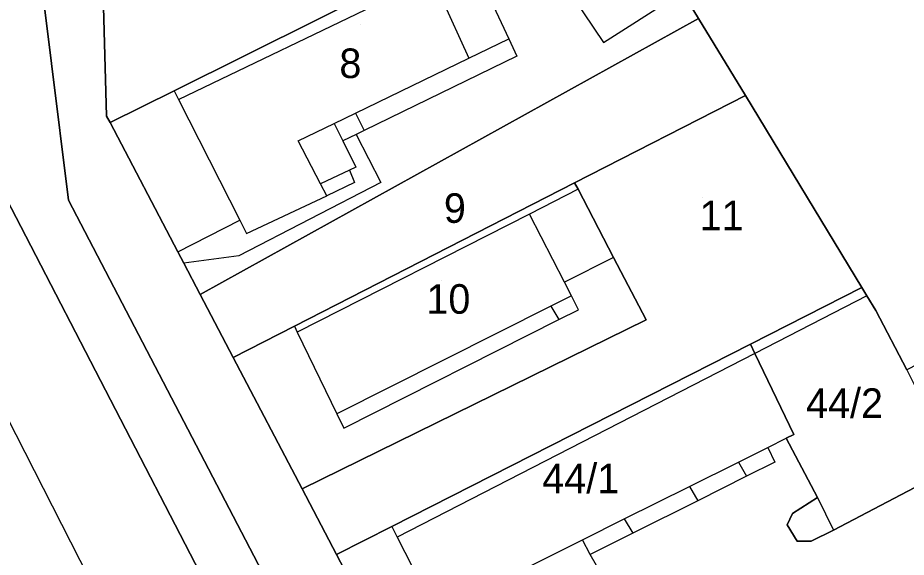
# Model space of a CAD drawing. Extents: x -263943 to -261149, y -1236934 to -1230686.
# Drawn here: x -262965.3 to -262905.2, y -1235602.8 to -1235566.2 of the extents above; entities that cross this region are included whole.
import ezdxf

# ---------------------------------------------------------------- set-up
doc = ezdxf.new("R2010")
doc.units = 0
for name, color, linetype in [('body_kn', 7, 'Continuous'), ('kladpar_druhypozemkov', 7, 'Continuous'), ('kladpar_hranice', 7, 'Continuous'), ('kladpar_parcelnecisla', 7, 'Continuous'), ('kladpar_plochy', 7, 'Continuous'), ('zappar_hrandruhpozemk', 7, 'Continuous'), ('zuob_linie', 7, 'Continuous'), ('zuob_plochy', 7, 'Continuous')]:
    doc.layers.add(name, color=color, linetype=linetype)

msp = doc.modelspace()

# ---------------------------------------------------------------- linework, layer by layer
at = {"layer": 'body_kn'}
for p, q in [((-262919.25, -1235566.29), (-262919.25, -1235566.29)), ((-262932.1, -1235567.68), (-262932.1, -1235567.68)), ((-262925.69, -1235567.93), (-262925.69, -1235567.93)), ((-262931.55, -1235568.85), (-262931.55, -1235568.85)), ((-262934.79, -1235568.98), (-262934.79, -1235568.98)), ((-262934.79, -1235568.98), (-262934.79, -1235568.98)), ((-262954.75, -1235571.19), (-262954.75, -1235571.19)), ((-262954.75, -1235571.19), (-262954.75, -1235571.19)), ((-262954.45, -1235571.78), (-262954.45, -1235571.78)), ((-262916.08, -1235571.52), (-262916.08, -1235571.52)), ((-262959.32, -1235572.92), (-262959.32, -1235572.92)), ((-262942.48, -1235572.7), (-262942.48, -1235572.7)), ((-262942.48, -1235572.7), (-262942.48, -1235572.7)), ((-262959.07, -1235573.34), (-262959.07, -1235573.34)), ((-262943.92, -1235573.4), (-262943.92, -1235573.4)), ((-262943.92, -1235573.4), (-262943.92, -1235573.4)), ((-262942.43, -1235574.16), (-262942.43, -1235574.16)), ((-262942.43, -1235574.16), (-262942.43, -1235574.16)), ((-262941.89, -1235573.89), (-262941.89, -1235573.89)), ((-262941.89, -1235573.89), (-262941.89, -1235573.89)), ((-262946.34, -1235574.57), (-262946.34, -1235574.57)), ((-262943.33, -1235574.59), (-262943.33, -1235574.59)), ((-262942.87, -1235576.57), (-262942.87, -1235576.57)), ((-262942.44, -1235576.37), (-262942.44, -1235576.37)), ((-262944.83, -1235577.48), (-262944.83, -1235577.48)), ((-262942.53, -1235577.39), (-262942.53, -1235577.39)), ((-262940.75, -1235577.39), (-262940.75, -1235577.39)), ((-262927.64, -1235577.43), (-262927.64, -1235577.43)), ((-262927.41, -1235577.86), (-262927.41, -1235577.86)), ((-262927.41, -1235577.86), (-262927.41, -1235577.86)), ((-262944.4, -1235578.31), (-262944.4, -1235578.31)), ((-262944.4, -1235578.31), (-262944.4, -1235578.31)), ((-262961.89, -1235578.6), (-262961.89, -1235578.6)), ((-262961.89, -1235578.6), (-262961.89, -1235578.6)), ((-262930.7, -1235579.54), (-262930.7, -1235579.54)), ((-262930.7, -1235579.54), (-262930.7, -1235579.54)), ((-262965.12, -1235580.37), (-262965.12, -1235580.37)), ((-262950.3, -1235579.94), (-262950.3, -1235579.94)), ((-262950.3, -1235579.94), (-262950.3, -1235579.94)), ((-262949.84, -1235580.84), (-262949.84, -1235580.84)), ((-262954.49, -1235582.09), (-262954.49, -1235582.09)), ((-262954.49, -1235582.09), (-262954.49, -1235582.09)), ((-262950.36, -1235582.37), (-262950.36, -1235582.37)), ((-262925.01, -1235582.47), (-262925.01, -1235582.47)), ((-262925.01, -1235582.47), (-262925.01, -1235582.47)), ((-262954.09, -1235582.85), (-262954.09, -1235582.85)), ((-262928.33, -1235584.15), (-262928.33, -1235584.15)), ((-262928.33, -1235584.15), (-262928.33, -1235584.15)), ((-262908.2, -1235584.51), (-262908.2, -1235584.51)), ((-262952.98, -1235584.97), (-262952.98, -1235584.97)), ((-262927.86, -1235585.06), (-262927.86, -1235585.06)), ((-262927.86, -1235585.06), (-262927.86, -1235585.06)), ((-262907.86, -1235585.07), (-262907.86, -1235585.07)), ((-262907.86, -1235585.07), (-262907.86, -1235585.07)), ((-262929.26, -1235585.76), (-262929.26, -1235585.76)), ((-262929.26, -1235585.76), (-262929.26, -1235585.76)), ((-262927.37, -1235586.01), (-262927.37, -1235586.01)), ((-262907.25, -1235586.07), (-262907.25, -1235586.07)), ((-262928.7, -1235586.68), (-262928.7, -1235586.68)), ((-262922.79, -1235586.7), (-262922.79, -1235586.7)), ((-262922.79, -1235586.7), (-262922.79, -1235586.7)), ((-262946.6, -1235587.13), (-262946.6, -1235587.13)), ((-262946.6, -1235587.13), (-262946.6, -1235587.13)), ((-262946.41, -1235587.53), (-262946.41, -1235587.53)), ((-262946.41, -1235587.53), (-262946.41, -1235587.53)), ((-262915.74, -1235588.34), (-262915.74, -1235588.34)), ((-262950.74, -1235589.25), (-262950.74, -1235589.25)), ((-262915.44, -1235588.97), (-262915.44, -1235588.97)), ((-262915.44, -1235588.97), (-262915.44, -1235588.97)), ((-262943.73, -1235593.06), (-262943.73, -1235593.06)), ((-262943.73, -1235593.06), (-262943.73, -1235593.06)), ((-262943.27, -1235594.02), (-262943.27, -1235594.02)), ((-262913.31, -1235594.71), (-262913.31, -1235594.71)), ((-262913.31, -1235594.71), (-262913.31, -1235594.71)), ((-262912.8, -1235594.46), (-262912.8, -1235594.46)), ((-262914.57, -1235595.34), (-262914.57, -1235595.34)), ((-262916.54, -1235596.32), (-262916.54, -1235596.32)), ((-262916.54, -1235596.32), (-262916.54, -1235596.32)), ((-262914.08, -1235596.32), (-262914.08, -1235596.32)), ((-262916, -1235597.28), (-262916, -1235597.28)), ((-262946.08, -1235598.13), (-262946.08, -1235598.13)), ((-262919.86, -1235597.97), (-262919.86, -1235597.97)), ((-262919.86, -1235597.97), (-262919.86, -1235597.97)), ((-262919.31, -1235598.94), (-262919.31, -1235598.94)), ((-262911.2, -1235598.71), (-262911.2, -1235598.71)), ((-262911.2, -1235598.71), (-262911.2, -1235598.71)), ((-262924.28, -1235600.17), (-262924.28, -1235600.17)), ((-262924.28, -1235600.17), (-262924.28, -1235600.17)), ((-262912.9, -1235599.81), (-262912.9, -1235599.81)), ((-262940.02, -1235600.67), (-262940.02, -1235600.67)), ((-262940.02, -1235600.67), (-262940.02, -1235600.67)), ((-262913.25, -1235600.57), (-262913.25, -1235600.57)), ((-262939.64, -1235601.41), (-262939.64, -1235601.41)), ((-262939.64, -1235601.41), (-262939.64, -1235601.41)), ((-262923.69, -1235601.13), (-262923.69, -1235601.13)), ((-262910.11, -1235600.92), (-262910.11, -1235600.92)), ((-262927.11, -1235601.58), (-262927.11, -1235601.58)), ((-262912.57, -1235601.68), (-262912.57, -1235601.68)), ((-262911.64, -1235601.68), (-262911.64, -1235601.68)), ((-262943.76, -1235602.57), (-262943.76, -1235602.57)), ((-262926.58, -1235602.57), (-262926.58, -1235602.57))]:
    msp.add_line(p, q, dxfattribs=at)
at = {"layer": 'kladpar_druhypozemkov'}
for p, q in [((-262942.16, -1235566.73), (-262942.16, -1235566.73)), ((-262935.91, -1235578.03), (-262935.91, -1235578.03)), ((-262918.96, -1235578.43), (-262918.96, -1235578.43)), ((-262936.66, -1235584.03), (-262936.66, -1235584.03)), ((-262909.06, -1235591.38), (-262909.06, -1235591.38)), ((-262927.41, -1235596.58), (-262927.41, -1235596.58))]:
    msp.add_line(p, q, dxfattribs=at)
at = {"layer": 'kladpar_hranice'}
for points in [[(-262892.28, -1235710.47), (-262940.98, -1235618.73), (-262961.89, -1235578.6), (-262964.19, -1235560.08), (-262962.22, -1235520.35), (-262962.16, -1235519.08), (-262957.32, -1235516.89), (-262956.98, -1235517.06), (-262957.08, -1235520.11), (-262957.43, -1235523.85), (-262959.84, -1235553.98), (-262959.32, -1235572.92), (-262959.07, -1235573.34), (-262954.49, -1235582.09), (-262954.09, -1235582.85), (-262952.98, -1235584.97), (-262950.74, -1235589.25), (-262946.08, -1235598.13), (-262943.76, -1235602.57), (-262941.04, -1235607.76), (-262938.08, -1235613.4), (-262933.36, -1235622.36), (-262928.9, -1235630.82), (-262925.85, -1235636.61)], [(-262961.89, -1235578.6), (-262940.98, -1235618.73), (-262892.28, -1235710.47), (-262846.58, -1235803.11), (-262815.95, -1235861.66), (-262747.15, -1236000.03), (-262778.52, -1235940.15), (-262819.01, -1235863.09), (-262849.55, -1235804.29), (-262897.55, -1235711.48), (-262944.38, -1235620.51), (-262941.66, -1235619.02), (-262944.02, -1235614.14), (-262946.91, -1235615.57), (-262965.12, -1235580.37), (-262989.13, -1235534.1), (-262970.6, -1235526.27), (-262962.22, -1235520.35), (-262964.19, -1235560.08), (-262961.89, -1235578.6)], [(-262989.13, -1235534.1), (-262965.12, -1235580.37), (-262946.91, -1235615.57), (-262948.44, -1235616.25), (-262945.91, -1235621.18), (-262944.38, -1235620.51), (-262897.55, -1235711.48), (-262849.55, -1235804.29), (-262819.01, -1235863.09)], [(-262932.36, -1235560.03), (-262935.05, -1235561.37), (-262940.11, -1235563.89), (-262954.75, -1235571.19), (-262959.07, -1235573.34), (-262959.32, -1235572.92), (-262959.84, -1235553.98), (-262956.71, -1235555.95), (-262955.62, -1235559.77), (-262951.63, -1235558.51), (-262938.75, -1235548.65), (-262937.26, -1235549.62), (-262937.06, -1235549.5), (-262931.46, -1235546.18), (-262925.21, -1235556.47), (-262931.31, -1235559.51), (-262932.36, -1235560.03)], [(-262925.21, -1235556.47), (-262923.1, -1235559.95), (-262922.28, -1235561.3), (-262920.34, -1235564.5), (-262919.25, -1235566.29), (-262952.98, -1235584.97), (-262954.09, -1235582.85), (-262954.49, -1235582.09), (-262959.07, -1235573.34), (-262954.75, -1235571.19), (-262940.11, -1235563.89), (-262935.05, -1235561.37), (-262932.36, -1235560.03), (-262931.31, -1235559.51), (-262925.21, -1235556.47)], [(-262887.03, -1235566.21), (-262880.91, -1235577.59), (-262905.15, -1235590.07), (-262907.25, -1235586.07), (-262907.86, -1235585.07), (-262908.2, -1235584.51), (-262916.08, -1235571.52), (-262919.25, -1235566.29), (-262920.34, -1235564.5)], [(-262946.6, -1235587.13), (-262950.74, -1235589.25), (-262952.98, -1235584.97), (-262919.25, -1235566.29), (-262916.08, -1235571.52), (-262927.64, -1235577.43), (-262946.6, -1235587.13)], [(-262940.02, -1235600.67), (-262943.76, -1235602.57), (-262946.08, -1235598.13), (-262922.79, -1235586.7), (-262925.01, -1235582.47), (-262927.41, -1235577.86), (-262927.64, -1235577.43), (-262916.08, -1235571.52), (-262908.2, -1235584.51), (-262915.74, -1235588.34), (-262940.02, -1235600.67)], [(-262922.79, -1235586.7), (-262946.08, -1235598.13), (-262950.74, -1235589.25), (-262946.6, -1235587.13), (-262927.64, -1235577.43), (-262927.41, -1235577.86), (-262925.01, -1235582.47), (-262922.79, -1235586.7)], [(-262899.14, -1235595.18), (-262901.9, -1235596.62), (-262910.11, -1235600.92), (-262911.64, -1235601.68), (-262912.57, -1235601.68), (-262913.25, -1235600.57), (-262912.9, -1235599.81), (-262911.2, -1235598.71), (-262913.31, -1235594.71), (-262912.8, -1235594.46), (-262915.44, -1235588.97), (-262915.74, -1235588.34), (-262908.2, -1235584.51), (-262907.86, -1235585.07), (-262907.25, -1235586.07), (-262905.15, -1235590.07), (-262904.13, -1235592.11), (-262901.5, -1235590.68), (-262899.14, -1235595.18)], [(-262913.31, -1235594.71), (-262911.2, -1235598.71), (-262912.9, -1235599.81), (-262913.25, -1235600.57), (-262912.57, -1235601.68), (-262911.64, -1235601.68), (-262910.11, -1235600.92), (-262901.9, -1235596.62), (-262897.98, -1235604.62), (-262913.56, -1235612.43), (-262920.48, -1235605.47), (-262936.29, -1235611.62), (-262938.08, -1235613.4), (-262941.04, -1235607.76), (-262943.76, -1235602.57), (-262940.02, -1235600.67), (-262915.74, -1235588.34), (-262915.44, -1235588.97), (-262912.8, -1235594.46), (-262913.31, -1235594.71)]]:
    msp.add_lwpolyline(points, dxfattribs=at)
at = {"layer": 'kladpar_plochy'}
for points in [[(-262892.28, -1235710.47), (-262940.98, -1235618.73), (-262961.89, -1235578.6), (-262964.19, -1235560.08), (-262962.22, -1235520.35), (-262962.16, -1235519.08), (-262957.32, -1235516.89), (-262956.98, -1235517.06), (-262957.08, -1235520.11), (-262957.43, -1235523.85), (-262959.84, -1235553.98), (-262959.32, -1235572.92), (-262959.07, -1235573.34), (-262954.49, -1235582.09), (-262954.09, -1235582.85), (-262952.98, -1235584.97), (-262950.74, -1235589.25), (-262946.08, -1235598.13), (-262943.76, -1235602.57), (-262941.04, -1235607.76), (-262938.08, -1235613.4), (-262933.36, -1235622.36), (-262928.9, -1235630.82), (-262925.85, -1235636.61)], [(-262989.13, -1235534.1), (-262965.12, -1235580.37), (-262946.91, -1235615.57), (-262948.44, -1235616.25), (-262945.91, -1235621.18), (-262944.38, -1235620.51), (-262897.55, -1235711.48), (-262849.55, -1235804.29), (-262819.01, -1235863.09), (-262778.52, -1235940.15), (-262747.15, -1236000.03), (-262733.97, -1236030.65), (-262710.45, -1236085.53), (-262699.7, -1236119.81), (-262681.18, -1236174.94)], [(-262887.03, -1235566.21), (-262880.91, -1235577.59), (-262905.15, -1235590.07), (-262907.25, -1235586.07), (-262907.86, -1235585.07), (-262908.2, -1235584.51), (-262916.08, -1235571.52), (-262919.25, -1235566.29), (-262920.34, -1235564.5)]]:
    msp.add_lwpolyline(points, dxfattribs=at)
for points in [[(-262961.89, -1235578.6), (-262940.98, -1235618.73), (-262892.28, -1235710.47), (-262846.58, -1235803.11), (-262815.95, -1235861.66), (-262747.15, -1236000.03), (-262778.52, -1235940.15), (-262819.01, -1235863.09), (-262849.55, -1235804.29), (-262897.55, -1235711.48), (-262944.38, -1235620.51), (-262941.66, -1235619.02), (-262944.02, -1235614.14), (-262946.91, -1235615.57), (-262965.12, -1235580.37), (-262989.13, -1235534.1), (-262970.6, -1235526.27), (-262962.22, -1235520.35), (-262964.19, -1235560.08)], [(-262932.36, -1235560.03), (-262935.05, -1235561.37), (-262940.11, -1235563.89), (-262954.75, -1235571.19), (-262959.07, -1235573.34), (-262959.32, -1235572.92), (-262959.84, -1235553.98), (-262956.71, -1235555.95), (-262955.62, -1235559.77), (-262951.63, -1235558.51), (-262938.75, -1235548.65), (-262937.26, -1235549.62), (-262937.06, -1235549.5), (-262931.46, -1235546.18), (-262925.21, -1235556.47), (-262931.31, -1235559.51)], [(-262925.21, -1235556.47), (-262923.1, -1235559.95), (-262922.28, -1235561.3), (-262920.34, -1235564.5), (-262919.25, -1235566.29), (-262952.98, -1235584.97), (-262954.09, -1235582.85), (-262954.49, -1235582.09), (-262959.07, -1235573.34), (-262954.75, -1235571.19), (-262940.11, -1235563.89), (-262935.05, -1235561.37), (-262932.36, -1235560.03), (-262931.31, -1235559.51)], [(-262946.6, -1235587.13), (-262950.74, -1235589.25), (-262952.98, -1235584.97), (-262919.25, -1235566.29), (-262916.08, -1235571.52), (-262927.64, -1235577.43)], [(-262940.02, -1235600.67), (-262943.76, -1235602.57), (-262946.08, -1235598.13), (-262922.79, -1235586.7), (-262925.01, -1235582.47), (-262927.41, -1235577.86), (-262927.64, -1235577.43), (-262916.08, -1235571.52), (-262908.2, -1235584.51), (-262915.74, -1235588.34)], [(-262922.79, -1235586.7), (-262946.08, -1235598.13), (-262950.74, -1235589.25), (-262946.6, -1235587.13), (-262927.64, -1235577.43), (-262927.41, -1235577.86), (-262925.01, -1235582.47)], [(-262899.14, -1235595.18), (-262901.9, -1235596.62), (-262910.11, -1235600.92), (-262911.64, -1235601.68), (-262912.57, -1235601.68), (-262913.25, -1235600.57), (-262912.9, -1235599.81), (-262911.2, -1235598.71), (-262913.31, -1235594.71), (-262912.8, -1235594.46), (-262915.44, -1235588.97), (-262915.74, -1235588.34), (-262908.2, -1235584.51), (-262907.86, -1235585.07), (-262907.25, -1235586.07), (-262905.15, -1235590.07), (-262904.13, -1235592.11), (-262901.5, -1235590.68)], [(-262913.31, -1235594.71), (-262911.2, -1235598.71), (-262912.9, -1235599.81), (-262913.25, -1235600.57), (-262912.57, -1235601.68), (-262911.64, -1235601.68), (-262910.11, -1235600.92), (-262901.9, -1235596.62), (-262897.98, -1235604.62), (-262913.56, -1235612.43), (-262920.48, -1235605.47), (-262936.29, -1235611.62), (-262938.08, -1235613.4), (-262941.04, -1235607.76), (-262943.76, -1235602.57), (-262940.02, -1235600.67), (-262915.74, -1235588.34), (-262915.44, -1235588.97), (-262912.8, -1235594.46)]]:
    msp.add_lwpolyline(points, close=True, dxfattribs=at)
at = {"layer": 'zappar_hrandruhpozemk'}
for p, q in [((-262954.45, -1235571.78), (-262937.29, -1235563.52)), ((-262937.29, -1235563.52), (-262934.79, -1235568.98)), ((-262925.69, -1235567.93), (-262920.34, -1235564.5)), ((-262927.8, -1235564.78), (-262925.69, -1235567.93)), ((-262934.79, -1235568.98), (-262932.1, -1235567.68)), ((-262931.55, -1235568.85), (-262941.89, -1235573.89)), ((-262954.75, -1235571.19), (-262954.45, -1235571.78)), ((-262954.45, -1235571.78), (-262950.3, -1235579.94)), ((-262942.48, -1235572.7), (-262941.89, -1235573.89)), ((-262942.43, -1235574.16), (-262943.33, -1235574.59)), ((-262942.87, -1235576.57), (-262944.83, -1235577.48)), ((-262927.41, -1235577.86), (-262930.7, -1235579.54)), ((-262949.84, -1235580.84), (-262944.4, -1235578.31)), ((-262930.7, -1235579.54), (-262946.41, -1235587.53)), ((-262928.33, -1235584.15), (-262930.7, -1235579.54)), ((-262954.49, -1235582.09), (-262950.3, -1235579.94)), ((-262950.3, -1235579.94), (-262949.84, -1235580.84)), ((-262925.01, -1235582.47), (-262928.33, -1235584.15)), ((-262971.07, -1235583.49), (-262948.48, -1235627.71)), ((-262907.86, -1235585.07), (-262915.44, -1235588.97)), ((-262929.26, -1235585.76), (-262928.7, -1235586.68)), ((-262946.6, -1235587.13), (-262946.41, -1235587.53)), ((-262946.41, -1235587.53), (-262943.73, -1235593.06)), ((-262915.44, -1235588.97), (-262939.64, -1235601.41)), ((-262914.57, -1235595.34), (-262913.31, -1235594.71)), ((-262916.54, -1235596.32), (-262916, -1235597.28)), ((-262919.86, -1235597.97), (-262919.31, -1235598.94)), ((-262911.2, -1235598.71), (-262910.11, -1235600.92)), ((-262924.28, -1235600.17), (-262923.69, -1235601.13)), ((-262940.02, -1235600.67), (-262939.64, -1235601.41))]:
    msp.add_line(p, q, dxfattribs=at)
for points in [[(-262933.32, -1235565.07), (-262932.1, -1235567.68), (-262931.55, -1235568.85)], [(-262946.34, -1235574.57), (-262943.92, -1235573.4), (-262942.48, -1235572.7), (-262934.79, -1235568.98)], [(-262943.92, -1235573.4), (-262943.33, -1235574.59), (-262942.44, -1235576.37), (-262942.87, -1235576.57)], [(-262941.89, -1235573.89), (-262942.43, -1235574.16), (-262940.75, -1235577.39), (-262950.36, -1235582.37), (-262954.09, -1235582.85)], [(-262944.4, -1235578.31), (-262944.83, -1235577.48), (-262946.34, -1235574.57)], [(-262942.87, -1235576.57), (-262942.53, -1235577.39), (-262944.4, -1235578.31)], [(-262943.73, -1235593.06), (-262943.27, -1235594.02), (-262928.7, -1235586.68), (-262927.37, -1235586.01), (-262927.86, -1235585.06), (-262928.33, -1235584.15)], [(-262927.86, -1235585.06), (-262929.26, -1235585.76), (-262943.73, -1235593.06)], [(-262939.64, -1235601.41), (-262937.03, -1235606.52), (-262929.86, -1235602.95), (-262927.11, -1235601.58), (-262924.28, -1235600.17), (-262919.86, -1235597.97), (-262916.54, -1235596.32), (-262914.57, -1235595.34)], [(-262914.57, -1235595.34), (-262914.08, -1235596.32), (-262916, -1235597.28), (-262919.31, -1235598.94), (-262923.69, -1235601.13), (-262926.58, -1235602.57)], [(-262926.16, -1235603.33), (-262926.58, -1235602.57), (-262927.11, -1235601.58)]]:
    msp.add_lwpolyline(points, dxfattribs=at)
at = {"layer": 'zuob_linie'}
for points in [[(-262989.13, -1235534.1), (-262965.12, -1235580.37), (-262946.91, -1235615.57), (-262944.02, -1235614.14), (-262941.66, -1235619.02), (-262944.38, -1235620.51), (-262897.55, -1235711.48), (-262849.55, -1235804.29), (-262819.01, -1235863.09), (-262778.52, -1235940.15), (-262747.15, -1236000.03), (-262733.97, -1236030.65), (-262710.45, -1236085.53), (-262699.7, -1236119.81), (-262681.18, -1236174.94)], [(-262681.18, -1236174.94), (-262699.7, -1236119.81), (-262710.45, -1236085.53), (-262733.97, -1236030.65), (-262747.15, -1236000.03), (-262778.52, -1235940.15), (-262819.01, -1235863.09), (-262849.55, -1235804.29), (-262897.55, -1235711.48), (-262944.38, -1235620.51), (-262941.66, -1235619.02), (-262944.02, -1235614.14), (-262946.91, -1235615.57), (-262965.12, -1235580.37), (-262989.13, -1235534.1)]]:
    msp.add_lwpolyline(points, dxfattribs=at)
at = {"layer": 'zuob_plochy'}
for points in [[(-262989.13, -1235534.1), (-262965.12, -1235580.37), (-262946.91, -1235615.57), (-262944.02, -1235614.14), (-262941.66, -1235619.02), (-262944.38, -1235620.51), (-262897.55, -1235711.48), (-262849.55, -1235804.29), (-262819.01, -1235863.09), (-262778.52, -1235940.15), (-262747.15, -1236000.03), (-262733.97, -1236030.65), (-262710.45, -1236085.53), (-262699.7, -1236119.81), (-262681.18, -1236174.94)], [(-262681.18, -1236174.94), (-262699.7, -1236119.81), (-262710.45, -1236085.53), (-262733.97, -1236030.65), (-262747.15, -1236000.03), (-262778.52, -1235940.15), (-262819.01, -1235863.09), (-262849.55, -1235804.29), (-262897.55, -1235711.48), (-262944.38, -1235620.51), (-262941.66, -1235619.02), (-262944.02, -1235614.14), (-262946.91, -1235615.57), (-262965.12, -1235580.37), (-262989.13, -1235534.1)]]:
    msp.add_lwpolyline(points, dxfattribs=at)

# ---------------------------------------------------------------- texts
at = {"layer": 'kladpar_parcelnecisla'}
for s, p in [('8', (-262943.561, -1235570.33)), ('9', (-262936.487, -1235580.13)), ('11', (-262919.179, -1235580.63)), ('10', (-262937.67, -1235586.28)), ('44/2', (-262911.975, -1235593.33)), ('44/1', (-262929.829, -1235598.43))]:
    msp.add_text(s, height=2, dxfattribs=at).set_placement(p)

doc.saveas('drawing.dxf')
